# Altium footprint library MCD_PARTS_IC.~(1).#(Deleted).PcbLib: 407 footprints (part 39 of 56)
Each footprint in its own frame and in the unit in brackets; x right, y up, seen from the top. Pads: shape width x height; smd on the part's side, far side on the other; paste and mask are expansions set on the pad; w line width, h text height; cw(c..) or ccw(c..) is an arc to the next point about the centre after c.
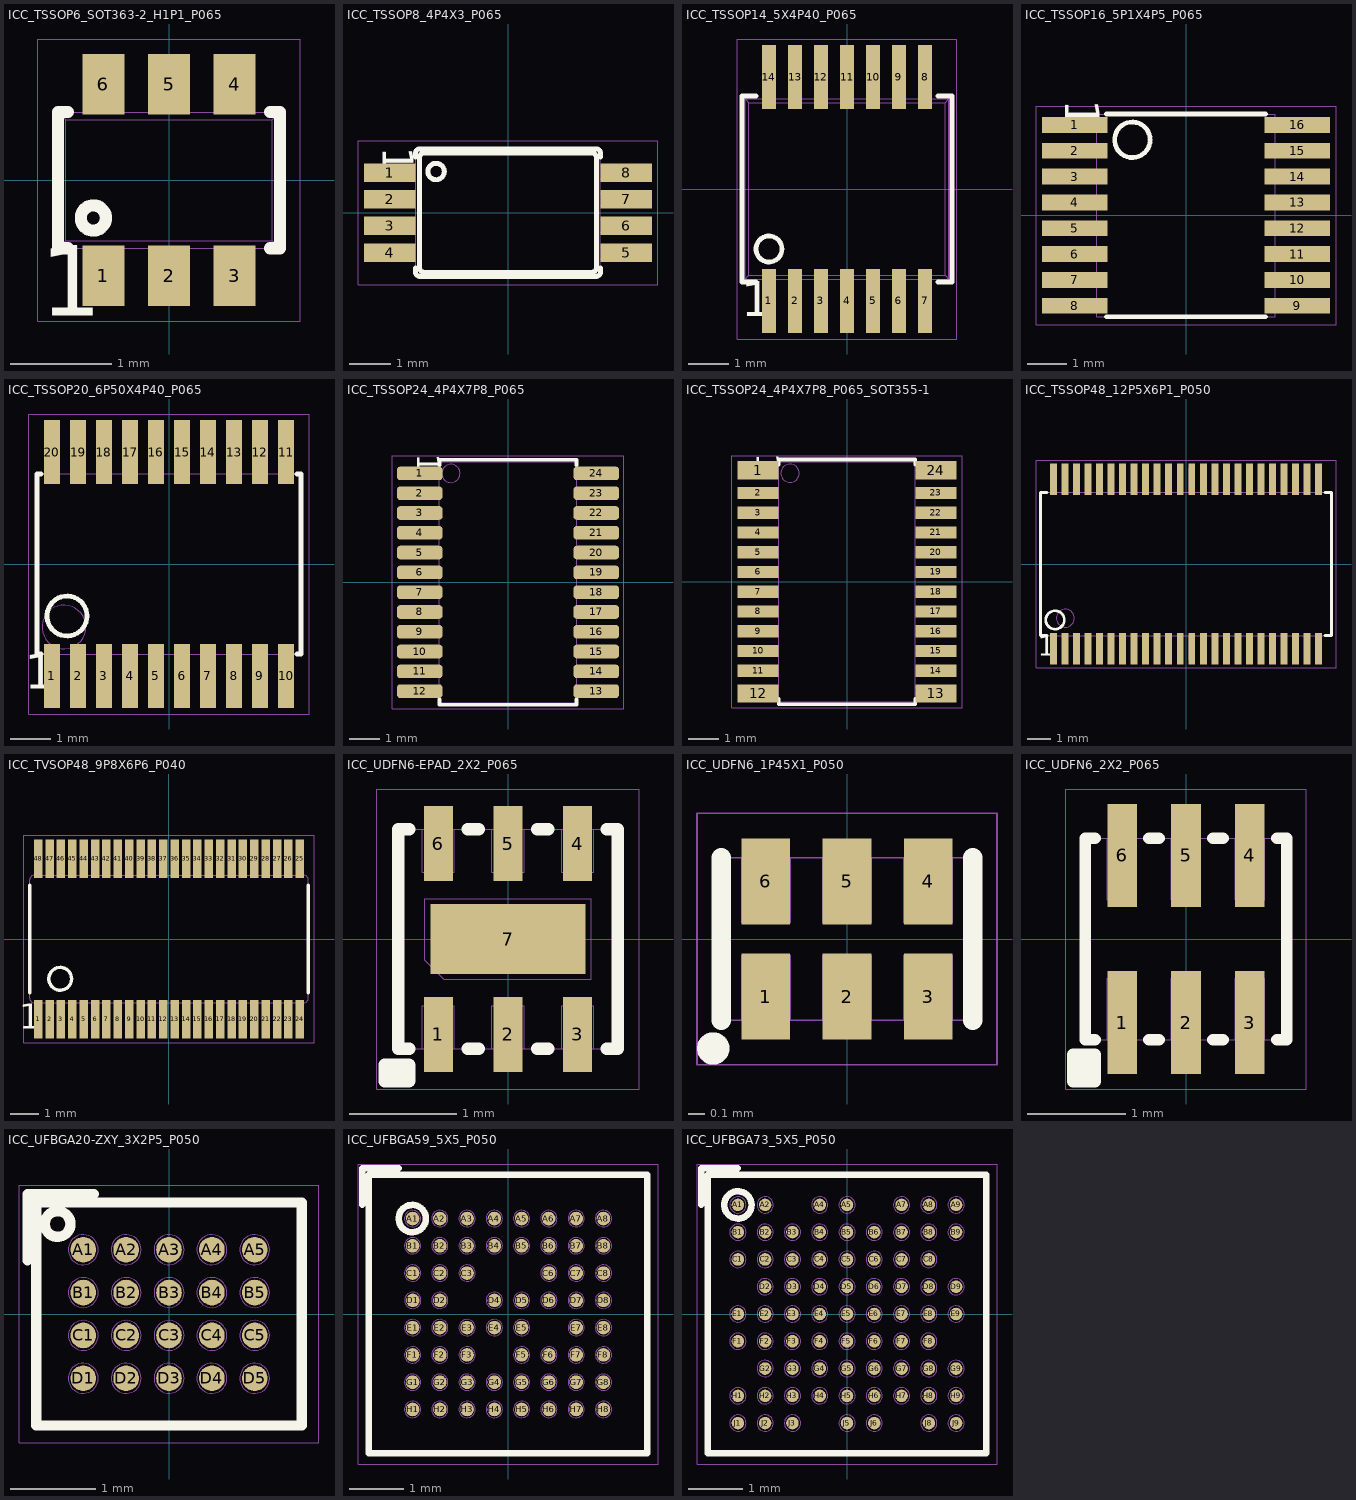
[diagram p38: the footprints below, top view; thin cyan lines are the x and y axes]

## ICC_TSSOP6_SOT363-2_H1P1_P065 [mm]
height 1.1
pads (6):
  rect 0.42x0.6 smd mask+0.05: 1(-0.65,-0.95) 2(0,-0.95) 3(0.65,-0.95) 4(0.65,0.95) 5(0,0.95) 6(-0.65,0.95)
Top Overlay:
  circle w0.12: c-0.75,-0.375 r0.125
  lines w0.12: -1,-0.675 -1.1,-0.675 -1.1,0.675 -1,0.675 ; 1,-0.675 1.1,-0.675 1.1,0.675 1,0.675
  text "1" at -1.275,-1.575 h1.2
M14-Top Assembly:
  circle w0.01: c-0.75,-0.375 r0.125
  lines w0.01: -0.8,-0.675 -0.8,-1.2 -0.5,-1.2 -0.5,-0.675 ; -0.8,0.675 -0.8,1.2 -0.5,1.2 -0.5,0.675 ; -0.15,-0.675 -0.15,-1.2 0.15,-1.2 0.15,-0.675 ; -0.15,0.675 -0.15,1.2 0.15,1.2 0.15,0.675 ; 0.5,-0.675 0.5,-1.2 0.8,-1.2 0.8,-0.675 ; 0.5,0.675 0.5,1.2 0.8,1.2 0.8,0.675 ; -1.1,-0.675 -1.025,-0.6 ; -1.1,-0.675 -1.1,0.675 ; -1.1,-0.675 1.1,-0.675 ; -1.1,0.675 -1.025,0.6 ; -1.1,0.675 1.1,0.675 ; -1.025,-0.6 1.025,-0.6 ; -1.025,-0.6 -1.025,0.6 ; -1.025,0.6 1.025,0.6 ; 1.025,-0.6 1.1,-0.675 ; 1.025,-0.6 1.025,0.6 ; 1.025,0.6 1.1,0.675 ; 1.1,-0.675 1.1,0.675
  text "'.Designator'" at -2,-0.5 h0.75
  text "4" at 0.55,0.725 h0.5
  text "5" at -0.1,0.725 h0.5
  text "6" at -0.75,0.725 h0.5
  text "1" at -0.725,-1.05 h0.5
  text "3" at 0.55,-1.05 h0.5
  text "2" at -0.1,-1.05 h0.5
M16-Top Courtyard:
  lines w0.01: -1.3,-1.4 -1.3,0.35 -1.3,1.4 -0.9,1.4 1.3,1.4 1.3,-1.4 -0.575,-1.4 -1.3,-1.4
3D body "SOT363.STEP": height 1.1, standoff 0, extent -1.1,-1.2 1.1,1.2
3D body: height 1.1, standoff 0, extent -1.1,-0.675 1.1,0.675

## ICC_TSSOP8_4P4X3_P065 [mm] "MCD-01888"
height 1.2
pads (8):
  rect 1.25x0.45 smd mask+0.05: 1(-2.875,0.975) 2(-2.875,0.325) 3(-2.875,-0.325) 4(-2.875,-0.975) 5(2.875,-0.975) 6(2.875,-0.325) 7(2.875,0.325) 8(2.875,0.975)
Top Overlay:
  circle w0.12: c-1.75,1 r0.2
  lines w0.12: -2.25,-1.35 -2.25,-1.45 ccw(c-2.15,-1.45) -2.15,-1.55 2.15,-1.55 ccw(c2.15,-1.45) 2.25,-1.45 2.25,-1.35 ; -2.25,1.35 -2.25,1.45 cw(c-2.15,1.45) -2.15,1.55 2.15,1.55 cw(c2.15,1.45) 2.25,1.45 2.25,1.35 ; -2.15,-1.35 ccw(c-2.05,-1.35) -2.05,-1.45 2.05,-1.45 ccw(c2.05,-1.35) 2.15,-1.35 2.15,1.35 ccw(c2.05,1.35) 2.05,1.45 -2.05,1.45 ccw(c-2.05,1.35) -2.15,1.35 -2.15,-1.35
  text "1" at -3.3,1.6 h1.3
M14-Top Assembly:
  circle w0.01: c-1.75,1 r0.2
  lines w0.01: -2.25,-1.125 -3.3,-1.125 -3.3,-0.825 -2.25,-0.825 ; -2.25,-0.475 -3.3,-0.475 -3.3,-0.175 -2.25,-0.175 ; -2.25,0.175 -3.3,0.175 -3.3,0.475 -2.25,0.475 ; -2.25,0.825 -3.3,0.825 -3.3,1.125 -2.25,1.125 ; 2.25,-1.125 3.3,-1.125 3.3,-0.825 2.25,-0.825 ; 2.25,-0.475 3.3,-0.475 3.3,-0.175 2.25,-0.175 ; 2.25,0.175 3.3,0.175 3.3,0.475 2.25,0.475 ; 2.25,0.825 3.3,0.825 3.3,1.125 2.25,1.125 ; -2.25,-1.45 ccw(c-2.15,-1.45) -2.15,-1.55 2.15,-1.55 ccw(c2.15,-1.45) 2.25,-1.45 2.25,1.45 ccw(c2.15,1.45) 2.15,1.55 -2.15,1.55 ccw(c-2.15,1.45) -2.25,1.45 -2.25,-1.45 ; -2.15,-1.35 ccw(c-2.05,-1.35) -2.05,-1.45 2.05,-1.45 ccw(c2.05,-1.35) 2.15,-1.35 2.15,1.35 ccw(c2.05,1.35) 2.05,1.45 -2.05,1.45 ccw(c-2.05,1.35) -2.15,1.35 -2.15,-1.35
  text "'.Designator'" at -2,-0.5 h0.75
  text "1" at -2.625,0.825 h0.5
  text "4" at -2.725,-1.125 h0.5
  text "5" at 2.5,-1.125 h0.5
  text "8" at 2.5,0.825 h0.5
M16-Top Courtyard:
  lines w0.01: -3.65,-1.75 3.65,-1.75 3.65,1.75 -2.25,1.75 -3.65,1.75 -3.65,-1.75
3D body: height 1.21, standoff 1.2, extent -2.098,0.901 -1.6,1.4
3D body: height 1.2, standoff 0, extent -2.25,-1.55 2.25,1.55
3D body "TSS0P8-1.STEP": height 1.09, standoff 0, extent -3.147,-1.5 3.133,1.5
3D body: height 1.1, standoff 1.09, extent -1.873,0.775 -1.475,1.175

## ICC_TSSOP14_5X4P40_P065 [mm]
height 1.2
pads (14):
  rect 0.35x1.6 smd mask+0.05: 1(-1.95,-2.8) 2(-1.3,-2.8) 3(-0.65,-2.8) 4(0,-2.8) 5(0.65,-2.8) 6(1.3,-2.8) 7(1.95,-2.8) 8(1.95,2.8) 9(1.3,2.8) 10(0.65,2.8) 11(0,2.8) 12(-0.65,2.8) 13(-1.3,2.8) 14(-1.95,2.8)
Top Overlay:
  circle w0.12: c-1.95,-1.5 r0.325
  lines w0.12: -2.275,-2.325 -2.625,-2.325 -2.625,2.325 -2.275,2.325 ; 2.275,-2.325 2.625,-2.325 2.625,2.325 2.275,2.325
  text "1" at -2.65,-3.475 h1.5
M14-Top Assembly:
  lines w0.01: -2.55,2.24 -2.55,-2.25 ; -2.55,-2.25 2.55,-2.25 ; -2.55,-2.25 -2.45,-2.15 ; -2.45,-2.15 2.45,-2.15 ; -2.45,-2.15 -2.45,2.15 ; -2.45,2.15 2.45,2.15 ; -2.45,2.15 -2.55,2.25 2.55,2.25 ; 2.45,-2.15 2.45,2.15 ; 2.45,-2.15 2.55,-2.25 ; 2.45,2.15 2.55,2.25 ; 2.55,-2.25 2.55,2.25 ; -2.075,-3.3 -1.825,-3.3 -1.825,-2.25 -2.075,-2.25 -2.075,-3.3 ; -2.075,2.25 -1.825,2.25 -1.825,3.3 -2.075,3.3 -2.075,2.25 ; -1.425,-3.3 -1.175,-3.3 -1.175,-2.25 -1.425,-2.25 -1.425,-3.3 ; -1.425,2.25 -1.175,2.25 -1.175,3.3 -1.425,3.3 -1.425,2.25 ; -0.775,-3.3 -0.525,-3.3 -0.525,-2.25 -0.775,-2.25 -0.775,-3.3 ; -0.775,2.25 -0.525,2.25 -0.525,3.3 -0.775,3.3 -0.775,2.25 ; -0.125,-3.3 0.125,-3.3 0.125,-2.25 -0.125,-2.25 -0.125,-3.3 ; -0.125,2.25 0.125,2.25 0.125,3.3 -0.125,3.3 -0.125,2.25 ; 0.525,-3.3 0.775,-3.3 0.775,-2.25 0.525,-2.25 0.525,-3.3 ; 0.525,2.25 0.775,2.25 0.775,3.3 0.525,3.3 0.525,2.25 ; 1.175,-3.3 1.425,-3.3 1.425,-2.25 1.175,-2.25 1.175,-3.3 ; 1.175,2.25 1.425,2.25 1.425,3.3 1.175,3.3 1.175,2.25 ; 1.825,-3.3 2.075,-3.3 2.075,-2.25 1.825,-2.25 1.825,-3.3 ; 1.825,2.25 2.075,2.25 2.075,3.3 1.825,3.3 1.825,2.25
  text "'.Designator'" at -2,-0.5 h0.75
  text "8" at 1.75,2.475 h1
  text "14" at -2.35,2.5 h1
  text "1" at -2.075,-3.125 h1
  text "7" at 1.75,-3.1 h1
M16-Top Courtyard:
  lines w0.01: -2.75,-3.75 -2.75,3.75 2.75,3.75 2.75,-3.75 -2.75,-3.75
3D body "TSSOP-14_5X4P40_P065.STEP": height 1.2, standoff 0, extent -2.5,-3.2 2.5,3.2
3D body: height 1.2, standoff 0, extent -2.55,-2.25 2.55,2.25
3D body: height 1.21, standoff 1.2, extent -2.248,-1.799 -1.65,-1.2

## ICC_TSSOP16_5P1X4P5_P065 [mm]
height 1.2
pads (16):
  rect 1.65x0.4 smd mask+0.05: 1(-2.8,2.275) 2(-2.8,1.625) 3(-2.8,0.975) 4(-2.8,0.325) 5(-2.8,-0.325) 6(-2.8,-0.975) 7(-2.8,-1.625) 8(-2.8,-2.275) 9(2.8,-2.275) 10(2.8,-1.625) 11(2.8,-0.975) 12(2.8,-0.325) 13(2.8,0.325) 14(2.8,0.975) 15(2.8,1.625) 16(2.8,2.275)
Top Overlay:
  circle w0.12: c-1.35,1.9 r0.447
  lines w0.12: -2,-2.55 2,-2.55 ; -2,2.55 2,2.55
  text "1" at -3.325,2.925 h1.5
M14-Top Assembly:
  circle w0.01: c-1.35,1.9 r0.447
  lines w0.01: -2.25,-2.425 -3.3,-2.425 -3.3,-2.125 -2.25,-2.125 ; -2.25,-1.775 -3.3,-1.775 -3.3,-1.475 -2.25,-1.475 ; -2.25,-1.125 -3.3,-1.125 -3.3,-0.825 -2.25,-0.825 ; -2.25,-0.475 -3.3,-0.475 -3.3,-0.175 -2.25,-0.175 ; -2.25,0.175 -3.3,0.175 -3.3,0.475 -2.25,0.475 ; -2.25,0.825 -3.3,0.825 -3.3,1.125 -2.25,1.125 ; -2.25,1.475 -3.3,1.475 -3.3,1.775 -2.25,1.775 ; -2.25,2.125 -3.3,2.125 -3.3,2.425 -2.25,2.425 ; 2.25,-2.425 3.3,-2.425 3.3,-2.125 2.25,-2.125 ; 2.25,-1.775 3.3,-1.775 3.3,-1.475 2.25,-1.475 ; 2.25,-1.125 3.3,-1.125 3.3,-0.825 2.25,-0.825 ; 2.25,-0.475 3.3,-0.475 3.3,-0.175 2.25,-0.175 ; 2.25,0.175 3.3,0.175 3.3,0.475 2.25,0.475 ; 2.25,0.825 3.3,0.825 3.3,1.125 2.25,1.125 ; 2.25,1.475 3.3,1.475 3.3,1.775 2.25,1.775 ; 2.25,2.125 3.3,2.125 3.3,2.425 2.25,2.425 ; -2.25,-2.55 2.25,-2.55 2.25,2.55 -2.25,2.55 -2.25,-2.55
  text "'.Designator'" at -2,-0.5 h0.75
  text "1" at -2.875,2.35 h0.75
  text "8" at -2.875,-2.125 h0.75
  text "9" at 2.85,-2.45 h0.75
  text "16" at 2.9,1.95 h0.75
M16-Top Courtyard:
  lines w0.01: -3.775,-2.75 3.775,-2.75 3.775,2.75 -3.775,2.75 -3.775,-2.75
3D body "TSSOP16_5-1X4-5_P065.STEP": height 1, standoff 0, extent -3.2,-2.5 3.2,2.5
3D body: height 1.2, standoff 0, extent -2.255,-2.555 2.255,2.555

## ICC_TSSOP20_6P50X4P40_P065 [mm]
height 1.2
pads (20):
  rect 0.4x1.6 smd mask+0.05: 1(-2.925,-2.8) 2(-2.275,-2.8) 3(-1.625,-2.8) 4(-0.975,-2.8) 5(-0.325,-2.8) 6(0.325,-2.8) 7(0.975,-2.8) 8(1.625,-2.8) 9(2.275,-2.8) 10(2.925,-2.8) 11(2.925,2.8) 12(2.275,2.8) 13(1.625,2.8) 14(0.975,2.8) 15(0.325,2.8) 16(-0.325,2.8) 17(-0.975,2.8) 18(-1.625,2.8) 19(-2.275,2.8) 20(-2.925,2.8)
Top Overlay:
  circle w0.12: c-2.55,-1.3 r0.5
  lines w0.12: -3.2,-2.25 -3.3,-2.25 -3.3,2.25 -3.2,2.25 ; 3.2,-2.25 3.3,-2.25 3.3,2.25 3.2,2.25
  text "1" at -3.6,-3.4 h1.5
M14-Top Assembly:
  circle w0.01: c-2.625,-1.575 r0.548
  lines w0.01: -3.025,-2.25 -3.025,-3.3 -2.825,-3.3 -2.825,-2.25 ; -3.025,2.25 -3.025,3.3 -2.825,3.3 -2.825,2.25 ; -2.375,-2.25 -2.375,-3.3 -2.175,-3.3 -2.175,-2.25 ; -2.375,2.25 -2.375,3.3 -2.175,3.3 -2.175,2.25 ; -1.725,-2.25 -1.725,-3.3 -1.525,-3.3 -1.525,-2.25 ; -1.725,2.25 -1.725,3.3 -1.525,3.3 -1.525,2.25 ; -1.075,-2.25 -1.075,-3.3 -0.875,-3.3 -0.875,-2.25 ; -1.075,2.25 -1.075,3.3 -0.875,3.3 -0.875,2.25 ; -0.425,-2.25 -0.425,-3.3 -0.225,-3.3 -0.225,-2.25 ; -0.425,2.25 -0.425,3.3 -0.225,3.3 -0.225,2.25 ; 0.225,-2.25 0.225,-3.3 0.425,-3.3 0.425,-2.25 ; 0.225,2.25 0.225,3.3 0.425,3.3 0.425,2.25 ; 0.875,-2.25 0.875,-3.3 1.075,-3.3 1.075,-2.25 ; 0.875,2.25 0.875,3.3 1.075,3.3 1.075,2.25 ; 1.525,-2.25 1.525,-3.3 1.725,-3.3 1.725,-2.25 ; 1.525,2.25 1.525,3.3 1.725,3.3 1.725,2.25 ; 2.175,-2.25 2.175,-3.3 2.375,-3.3 2.375,-2.25 ; 2.175,2.25 2.175,3.3 2.375,3.3 2.375,2.25 ; 2.825,-2.25 2.825,-3.3 3.025,-3.3 3.025,-2.25 ; 2.825,2.25 2.825,3.3 3.025,3.3 3.025,2.25 ; -3.3,-2.25 3.3,-2.25 3.3,2.25 -3.3,2.25 -3.3,-2.25
  text "1" at -3.05,-3.075 h1
  text "10" at 2.525,-3.075 h1
  text "11" at 2.55,2.475 h1
  text "20" at -3.375,2.475 h1
  text "'.Designator'" at -2,-0.5 h0.75
M16-Top Courtyard:
  lines w0.01: -3.5,-3.75 3.5,-3.75 3.5,3.75 -3.5,3.75 -3.5,-3.75
3D body "TSSOP20_6P50X4P40_P065.STEP": height 1.2, standoff 0, extent -3.3,-3.3 3.3,3.3
3D body: height 1.2, standoff 0, extent -3.3,-2.25 3.3,2.25
3D body: height 1.21, standoff 1.2, extent -2.973,-1.924 -2.375,-1.326

## ICC_TSSOP24_4P4X7P8_P065 [mm]
height 1.2
pads (24):
  rrect50% 1.5x0.45 smd mask+0.05: 1(-2.9,3.575) 2(-2.9,2.925) 3(-2.9,2.275) 4(-2.9,1.625) 5(-2.9,0.975) 6(-2.9,0.325) 7(-2.9,-0.325) 8(-2.9,-0.975) 9(-2.9,-1.625) 10(-2.9,-2.275) 11(-2.9,-2.925) 12(-2.9,-3.575) 13(2.9,-3.575) 14(2.9,-2.925) 15(2.9,-2.275) 16(2.9,-1.625) 17(2.9,-0.975) 18(2.9,-0.325) 19(2.9,0.325) 20(2.9,0.975) 21(2.9,1.625) 22(2.9,2.275) 23(2.9,2.925) 24(2.9,3.575)
Top Overlay:
  lines w0.12: -2.25,-3.85 -2.25,-4.025 2.25,-4.025 2.25,-3.85 ; -2.25,3.85 -2.25,4.025 2.25,4.025 2.25,3.85
  text "1" at -3.241,4.225 h1.3
M14-Top Assembly:
  circle w0.01: c-1.875,3.575 r0.3
  lines w0.01: -3.3,-3.675 -3.3,-3.475 -2.25,-3.475 -2.25,-3.675 -3.3,-3.675 ; -3.3,-3.025 -3.3,-2.825 -2.25,-2.825 -2.25,-3.025 -3.3,-3.025 ; -3.3,-2.375 -3.3,-2.175 -2.25,-2.175 -2.25,-2.375 -3.3,-2.375 ; -3.3,-1.725 -3.3,-1.525 -2.25,-1.525 -2.25,-1.725 -3.3,-1.725 ; -3.3,-1.075 -3.3,-0.875 -2.25,-0.875 -2.25,-1.075 -3.3,-1.075 ; -3.3,-0.425 -3.3,-0.225 -2.25,-0.225 -2.25,-0.425 -3.3,-0.425 ; -3.3,0.225 -3.3,0.425 -2.25,0.425 -2.25,0.225 -3.3,0.225 ; -3.3,0.875 -3.3,1.075 -2.25,1.075 -2.25,0.875 -3.3,0.875 ; -3.3,1.525 -3.3,1.725 -2.25,1.725 -2.25,1.525 -3.3,1.525 ; -3.3,2.175 -3.3,2.375 -2.25,2.375 -2.25,2.175 -3.3,2.175 ; -3.3,2.825 -3.3,3.025 -2.25,3.025 -2.25,2.825 -3.3,2.825 ; -3.3,3.475 -3.3,3.675 -2.25,3.675 -2.25,3.475 -3.3,3.475 ; -2.25,-3.95 -2.25,3.95 2.25,3.95 2.25,-3.95 -2.25,-3.95 ; 2.25,-3.675 2.25,-3.475 3.3,-3.475 3.3,-3.675 2.25,-3.675 ; 2.25,-3.025 2.25,-2.825 3.3,-2.825 3.3,-3.025 2.25,-3.025 ; 2.25,-2.375 2.25,-2.175 3.3,-2.175 3.3,-2.375 2.25,-2.375 ; 2.25,-1.725 2.25,-1.525 3.3,-1.525 3.3,-1.725 2.25,-1.725 ; 2.25,-1.075 2.25,-0.875 3.3,-0.875 3.3,-1.075 2.25,-1.075 ; 2.25,-0.425 2.25,-0.225 3.3,-0.225 3.3,-0.425 2.25,-0.425 ; 2.25,0.225 2.25,0.425 3.3,0.425 3.3,0.225 2.25,0.225 ; 2.25,0.875 2.25,1.075 3.3,1.075 3.3,0.875 2.25,0.875 ; 2.25,1.525 2.25,1.725 3.3,1.725 3.3,1.525 2.25,1.525 ; 2.25,2.175 2.25,2.375 3.3,2.375 3.3,2.175 2.25,2.175 ; 2.25,2.825 2.25,3.025 3.3,3.025 3.3,2.825 2.25,2.825 ; 2.25,3.475 2.25,3.675 3.3,3.675 3.3,3.475 2.25,3.475
  text "24" at 2.375,4.025 h1
  text "13" at 2.375,-3.15 h1
  text "12" at -3,-3.15 h1
  text "1" at -3.025,3.725 h1
  text "'.Designator'" at -2,-0.5 h0.75
M16-Top Courtyard:
  lines w0.01: -3.8,-4.15 3.8,-4.15 3.8,4.15 -3.8,4.15 -3.8,-4.15
3D body "TSSOP24.STEP": height 1.2, standoff 0, extent -3.278,-3.95 3.278,3.95

## ICC_TSSOP24_4P4X7P8_P065_SOT355-1 [mm] "MCD-04154"
height 1.2
pads (24):
  rect 1.35x0.6 smd mask+0.05: 1(-2.925,3.675) 12(-2.925,-3.675) 13(2.925,-3.675) 24(2.925,3.675)
  rect 1.35x0.4 smd mask+0.05: 2(-2.925,2.925) 3(-2.925,2.275) 4(-2.925,1.625) 5(-2.925,0.975) 6(-2.925,0.325) 7(-2.925,-0.325) 8(-2.925,-0.975) 9(-2.925,-1.625) 10(-2.925,-2.275) 11(-2.925,-2.925) 14(2.925,-2.925) 15(2.925,-2.275) 16(2.925,-1.625) 17(2.925,-0.975) 18(2.925,-0.325) 19(2.925,0.325) 20(2.925,0.975) 21(2.925,1.625) 22(2.925,2.275) 23(2.925,2.925)
Top Overlay:
  lines w0.12: -2.25,-3.85 -2.25,-4.025 2.25,-4.025 2.25,-3.85 ; -2.25,3.85 -2.25,4.025 2.25,4.025 2.25,3.85
  text "1" at -3.241,4.225 h1.3
M14-Top Assembly:
  circle w0.01: c-1.875,3.575 r0.3
  lines w0.01: -3.3,-3.675 -3.3,-3.475 -2.25,-3.475 -2.25,-3.675 -3.3,-3.675 ; -3.3,-3.025 -3.3,-2.825 -2.25,-2.825 -2.25,-3.025 -3.3,-3.025 ; -3.3,-2.375 -3.3,-2.175 -2.25,-2.175 -2.25,-2.375 -3.3,-2.375 ; -3.3,-1.725 -3.3,-1.525 -2.25,-1.525 -2.25,-1.725 -3.3,-1.725 ; -3.3,-1.075 -3.3,-0.875 -2.25,-0.875 -2.25,-1.075 -3.3,-1.075 ; -3.3,-0.425 -3.3,-0.225 -2.25,-0.225 -2.25,-0.425 -3.3,-0.425 ; -3.3,0.225 -3.3,0.425 -2.25,0.425 -2.25,0.225 -3.3,0.225 ; -3.3,0.875 -3.3,1.075 -2.25,1.075 -2.25,0.875 -3.3,0.875 ; -3.3,1.525 -3.3,1.725 -2.25,1.725 -2.25,1.525 -3.3,1.525 ; -3.3,2.175 -3.3,2.375 -2.25,2.375 -2.25,2.175 -3.3,2.175 ; -3.3,2.825 -3.3,3.025 -2.25,3.025 -2.25,2.825 -3.3,2.825 ; -3.3,3.475 -3.3,3.675 -2.25,3.675 -2.25,3.475 -3.3,3.475 ; -2.25,-3.95 -2.25,3.95 2.25,3.95 2.25,-3.95 -2.25,-3.95 ; 2.25,-3.675 2.25,-3.475 3.3,-3.475 3.3,-3.675 2.25,-3.675 ; 2.25,-3.025 2.25,-2.825 3.3,-2.825 3.3,-3.025 2.25,-3.025 ; 2.25,-2.375 2.25,-2.175 3.3,-2.175 3.3,-2.375 2.25,-2.375 ; 2.25,-1.725 2.25,-1.525 3.3,-1.525 3.3,-1.725 2.25,-1.725 ; 2.25,-1.075 2.25,-0.875 3.3,-0.875 3.3,-1.075 2.25,-1.075 ; 2.25,-0.425 2.25,-0.225 3.3,-0.225 3.3,-0.425 2.25,-0.425 ; 2.25,0.225 2.25,0.425 3.3,0.425 3.3,0.225 2.25,0.225 ; 2.25,0.875 2.25,1.075 3.3,1.075 3.3,0.875 2.25,0.875 ; 2.25,1.525 2.25,1.725 3.3,1.725 3.3,1.525 2.25,1.525 ; 2.25,2.175 2.25,2.375 3.3,2.375 3.3,2.175 2.25,2.175 ; 2.25,2.825 2.25,3.025 3.3,3.025 3.3,2.825 2.25,2.825 ; 2.25,3.475 2.25,3.675 3.3,3.675 3.3,3.475 2.25,3.475
  text "24" at 2.375,4.025 h1
  text "13" at 2.375,-3.15 h1
  text "12" at -3,-3.15 h1
  text "1" at -3.025,3.725 h1
  text "'.Designator'" at 0,0 h0.75
M16-Top Courtyard:
  lines w0.01: -3.8,-4.15 3.8,-4.15 3.8,4.15 -3.8,4.15 -3.8,-4.15
3D body "TSSOP24.STEP": height 1.2, standoff 0, extent -3.278,-3.95 3.278,3.95

## ICC_TSSOP48_12P5X6P1_P050 [mm]
height 1.2
pads (48):
  rect 0.3x1.35 smd mask+0.05: 1(-5.75,-3.675) 2(-5.25,-3.675) 3(-4.75,-3.675) 4(-4.25,-3.675) 5(-3.75,-3.675) 6(-3.25,-3.675) 7(-2.75,-3.675) 8(-2.25,-3.675) 9(-1.75,-3.675) 10(-1.25,-3.675) 11(-0.75,-3.675) 12(-0.25,-3.675) 13(0.25,-3.675) 14(0.75,-3.675) 15(1.25,-3.675) 16(1.75,-3.675) 17(2.25,-3.675) 18(2.75,-3.675) 19(3.25,-3.675) 20(3.75,-3.675) 21(4.25,-3.675) 22(4.75,-3.675) 23(5.25,-3.675) 24(5.75,-3.675) 25(5.75,3.675) 26(5.25,3.675) 27(4.75,3.675) 28(4.25,3.675) 29(3.75,3.675) 30(3.25,3.675) 31(2.75,3.675) 32(2.25,3.675) 33(1.75,3.675) 34(1.25,3.675) 35(0.75,3.675) 36(0.25,3.675) 37(-0.25,3.675) 38(-0.75,3.675) 39(-1.25,3.675) 40(-1.75,3.675) 41(-2.25,3.675) 42(-2.75,3.675) 43(-3.25,3.675) 44(-3.75,3.675) 45(-4.25,3.675) 46(-4.75,3.675) 47(-5.25,3.675) 48(-5.75,3.675)
Top Overlay:
  circle w0.12: c-5.675,-2.425 r0.4
  lines w0.12: -6.025,-3.1 -6.3,-3.1 -6.3,3.1 -6.025,3.1 ; 6.025,-3.1 6.3,-3.1 6.3,3.1 6.025,3.1
  text "1" at -6.425,-4.275 h1.5
M14-Top Assembly:
  circle w0.01: c-5.225,-2.35 r0.391
  lines w0.01: -5.85,-3.1 -5.85,-4.15 -5.65,-4.15 -5.65,-3.1 ; -5.85,3.1 -5.85,4.15 -5.65,4.15 -5.65,3.1 ; -5.35,-3.1 -5.35,-4.15 -5.15,-4.15 -5.15,-3.1 ; -5.35,3.1 -5.35,4.15 -5.15,4.15 -5.15,3.1 ; -4.85,-3.1 -4.85,-4.15 -4.65,-4.15 -4.65,-3.1 ; -4.85,3.1 -4.85,4.15 -4.65,4.15 -4.65,3.1 ; -4.35,-3.1 -4.35,-4.15 -4.15,-4.15 -4.15,-3.1 ; -4.35,3.1 -4.35,4.15 -4.15,4.15 -4.15,3.1 ; -3.85,-3.1 -3.85,-4.15 -3.65,-4.15 -3.65,-3.1 ; -3.85,3.1 -3.85,4.15 -3.65,4.15 -3.65,3.1 ; -3.35,-3.1 -3.35,-4.15 -3.15,-4.15 -3.15,-3.1 ; -3.35,3.1 -3.35,4.15 -3.15,4.15 -3.15,3.1 ; -2.85,-3.1 -2.85,-4.15 -2.65,-4.15 -2.65,-3.1 ; -2.85,3.1 -2.85,4.15 -2.65,4.15 -2.65,3.1 ; -2.35,-3.1 -2.35,-4.15 -2.15,-4.15 -2.15,-3.1 ; -2.35,3.1 -2.35,4.15 -2.15,4.15 -2.15,3.1 ; -1.85,-3.1 -1.85,-4.15 -1.65,-4.15 -1.65,-3.1 ; -1.85,3.1 -1.85,4.15 -1.65,4.15 -1.65,3.1 ; -1.35,-3.1 -1.35,-4.15 -1.15,-4.15 -1.15,-3.1 ; -1.35,3.1 -1.35,4.15 -1.15,4.15 -1.15,3.1 ; -0.85,-3.1 -0.85,-4.15 -0.65,-4.15 -0.65,-3.1 ; -0.85,3.1 -0.85,4.15 -0.65,4.15 -0.65,3.1 ; -0.35,-3.1 -0.35,-4.15 -0.15,-4.15 -0.15,-3.1 ; -0.35,3.1 -0.35,4.15 -0.15,4.15 -0.15,3.1 ; 0.15,-3.1 0.15,-4.15 0.35,-4.15 0.35,-3.1 ; 0.15,3.1 0.15,4.15 0.35,4.15 0.35,3.1 ; 0.65,-3.1 0.65,-4.15 0.85,-4.15 0.85,-3.1 ; 0.65,3.1 0.65,4.15 0.85,4.15 0.85,3.1 ; 1.15,-3.1 1.15,-4.15 1.35,-4.15 1.35,-3.1 ; 1.15,3.1 1.15,4.15 1.35,4.15 1.35,3.1 ; 1.65,-3.1 1.65,-4.15 1.85,-4.15 1.85,-3.1 ; 1.65,3.1 1.65,4.15 1.85,4.15 1.85,3.1 ; 2.15,-3.1 2.15,-4.15 2.35,-4.15 2.35,-3.1 ; 2.15,3.1 2.15,4.15 2.35,4.15 2.35,3.1 ; 2.65,-3.1 2.65,-4.15 2.85,-4.15 2.85,-3.1 ; 2.65,3.1 2.65,4.15 2.85,4.15 2.85,3.1 ; 3.15,-3.1 3.15,-4.15 3.35,-4.15 3.35,-3.1 ; 3.15,3.1 3.15,4.15 3.35,4.15 3.35,3.1 ; 3.65,-3.1 3.65,-4.15 3.85,-4.15 3.85,-3.1 ; 3.65,3.1 3.65,4.15 3.85,4.15 3.85,3.1 ; 4.15,-3.1 4.15,-4.15 4.35,-4.15 4.35,-3.1 ; 4.15,3.1 4.15,4.15 4.35,4.15 4.35,3.1 ; 4.65,-3.1 4.65,-4.15 4.85,-4.15 4.85,-3.1 ; 4.65,3.1 4.65,4.15 4.85,4.15 4.85,3.1 ; 5.15,-3.1 5.15,-4.15 5.35,-4.15 5.35,-3.1 ; 5.15,3.1 5.15,4.15 5.35,4.15 5.35,3.1 ; 5.65,-3.1 5.65,-4.15 5.85,-4.15 5.85,-3.1 ; 5.65,3.1 5.65,4.15 5.85,4.15 5.85,3.1 ; -6.3,-3.1 -6.3,3.1 6.3,3.1 6.3,-3.1 -6.3,-3.1
  text "'.Designator'" at -2,-0.5 h0.75
  text "48" at -6.2,3.275 h1
  text "25" at 5.275,3.275 h1
  text "24" at 5.3,-3.925 h1
  text "1" at -5.875,-3.95 h1
M16-Top Courtyard:
  lines w0.01: -6.5,-4.5 6.5,-4.5 6.5,4.5 -6.5,4.5 -6.5,-4.5
3D body: height 1.2, standoff 0, extent -6.299,-3.099 6.299,3.099
3D body "TSSOP48.STEP": height 1.2, standoff 0, extent -6.25,-4.05 6.25,4.05

## ICC_TVSOP48_9P8X6P6_P040 [mm] "MCD-02226"
height 1.2
pads (48):
  rect 0.3x1.35 smd mask+0.05: 1(-4.6,-2.825) 2(-4.2,-2.825) 3(-3.8,-2.825) 4(-3.4,-2.825) 5(-3,-2.825) 6(-2.6,-2.825) 7(-2.2,-2.825) 8(-1.8,-2.825) 9(-1.4,-2.825) 10(-1,-2.825) 11(-0.6,-2.825) 12(-0.2,-2.825) 13(0.2,-2.825) 14(0.6,-2.825) 15(1,-2.825) 16(1.4,-2.825) 17(1.8,-2.825) 18(2.2,-2.825) 19(2.6,-2.825) 20(3,-2.825) 21(3.4,-2.825) 22(3.8,-2.825) 23(4.2,-2.825) 24(4.6,-2.825) 25(4.6,2.825) 26(4.2,2.825) 27(3.8,2.825) 28(3.4,2.825) 29(3,2.825) 30(2.6,2.825) 31(2.2,2.825) 32(1.8,2.825) 33(1.4,2.825) 34(1,2.825) 35(0.6,2.825) 36(0.2,2.825) 37(-0.2,2.825) 38(-0.6,2.825) 39(-1,2.825) 40(-1.4,2.825) 41(-1.8,2.825) 42(-2.2,2.825) 43(-2.6,2.825) 44(-3,2.825) 45(-3.4,2.825) 46(-3.8,2.825) 47(-4.2,2.825) 48(-4.6,2.825)
Top Overlay:
  circle w0.12: c-3.825,-1.4 r0.4
  lines w0.12: -4.9,-1.9 -4.9,1.9 ; 4.9,-1.9 4.9,1.9
  text "1" at -5.275,-3.45 h1.5
M14-Top Assembly:
  drawing of 153 lines, arcs and shapes, not listed
  text "1" at -4.75,-3.1 h1
  text "24" at 4.125,-3.075 h1
  text "25" at 4.15,2.5 h1
  text "48" at -5.1,2.5 h1
  text "'.Designator'" at -2,-0.5 h0.75
M16-Top Courtyard:
  lines w0.01: -5.1,-3.65 -5.1,3.65 5.1,3.65 5.1,-3.65 -5.1,-3.65
3D body: height 1.2, standoff 0, extent -4.9,-2.25 4.9,2.25
3D body "User Library-JEDEC-MO-194.STEP": height 1.2, standoff 0, extent -4.85,-3.2 4.85,3.2

## ICC_UDFN6-EPAD_2X2_P065 [mm] "MCD-02159"
height 0.55
pads (7):
  rect 0.27x0.7 smd mask+0.05: 1(-0.65,-0.89) 2(0,-0.89) 3(0.65,-0.89) 4(0.65,0.89) 5(0,0.89) 6(-0.65,0.89)
  rect 1.45x0.65 smd mask+0.05: 7(0,0)
Top Overlay:
  lines w0.12: -1.125,-1.325 -0.975,-1.175 -0.975,-1.2 -0.95,-1.175 ; -0.925,-1.025 -1.025,-1.025 -1.025,-1 -1.025,1.025 -0.925,1.025 ; -0.375,-1.025 -0.275,-1.025 ; -0.375,1.025 -0.275,1.025 ; 0.275,-1.025 0.375,-1.025 ; 0.275,1.025 0.375,1.025 ; 0.925,-1.025 1.025,-1.025 1.025,1 1.025,1.025 0.925,1.025 ; -1.15,-1.325 -1.15,-1.175 -0.925,-1.175 -0.925,-1.325 -1.15,-1.325
M14-Top Assembly:
  lines w0.01: -0.8,-1.025 -0.8,-0.625 -0.5,-0.625 -0.5,-1.025 ; -0.8,1.025 -0.8,0.625 -0.5,0.625 -0.5,1.025 ; -0.15,-1.025 -0.15,-0.625 0.15,-0.625 0.15,-1.025 ; -0.15,1.025 -0.15,0.625 0.15,0.625 0.15,1.025 ; 0.5,-1.025 0.5,-0.625 0.8,-0.625 0.8,-1.025 ; 0.5,1.025 0.5,0.625 0.8,0.625 0.8,1.025 ; -1.025,-1.025 1.025,-1.025 1.025,1.025 -1.025,1.025 -1.025,-1.025 ; -0.775,-0.2 -0.775,0.375 0.775,0.375 0.775,-0.375 -0.6,-0.375 -0.775,-0.2
  text "7" at -0.125,-0.175 h0.6
  text "'.Designator'" at -2,-0.5 h0.75
  text "1" at -0.725,-1.025 h0.6
  text "2" at -0.125,-1.025 h0.6
  text "3" at 0.525,-1.025 h0.6
  text "4" at 0.525,0.625 h0.6
  text "5" at -0.125,0.625 h0.6
  text "6" at -0.775,0.625 h0.6
M16-Top Courtyard:
  lines w0.01: -1.225,-1.4 -1.225,1.4 1.225,1.4 1.225,-1.4 -1.225,-1.4
3D body: height 0.56, standoff 0.55, extent -0.899,-0.9 -0.6,-0.6
3D body: height 0.55, standoff 0.05, extent -1.025,-1.025 1.025,1.025
3D body: height 0.05, standoff 0, extent -0.8,0.625 -0.5,1.025
3D body: height 0.05, standoff 0, extent -0.775,-0.375 0.775,0.375
3D body: height 0.05, standoff 0, extent -0.15,0.625 0.15,1.025
3D body: height 0.05, standoff 0, extent 0.5,0.625 0.8,1.025
3D body: height 0.05, standoff 0, extent -0.8,-1.025 -0.5,-0.625
3D body: height 0.05, standoff 0, extent -0.15,-1.025 0.15,-0.625
3D body: height 0.05, standoff 0, extent 0.5,-1.025 0.8,-0.625

## ICC_UDFN6_1P45X1_P050 [mm] "MCD-01509"
height 0.55
pads (6):
  rect 0.3x0.53 smd mask+0.05: 1(-0.5,-0.355) 2(0,-0.355) 3(0.5,-0.355) 4(0.5,0.355) 5(0,0.355) 6(-0.5,0.355)
Top Overlay:
  circle w0.1: c-0.825,-0.675 r0.05
  lines w0.12: -0.775,-0.5 -0.775,0.5 ; 0.775,-0.5 0.775,0.5
M14-Top Assembly:
  lines w0.01: -0.65,-0.5 -0.65,-0.1 -0.35,-0.1 -0.35,-0.5 ; -0.65,0.5 -0.65,0.1 -0.35,0.1 -0.35,0.5 ; -0.15,-0.5 -0.15,-0.1 0.15,-0.1 0.15,-0.5 ; -0.15,0.5 -0.15,0.1 0.15,0.1 0.15,0.5 ; 0.35,-0.5 0.35,-0.1 0.65,-0.1 0.65,-0.5 ; 0.35,0.5 0.35,0.1 0.65,0.1 0.65,0.5 ; -0.725,-0.5 -0.725,0.5 0.725,0.5 0.725,-0.5 -0.725,-0.5
  text "6" at -0.6,0.15 h0.5
  text "5" at -0.1,0.15 h0.5
  text "4" at 0.4,0.15 h0.5
  text "3" at 0.4,-0.475 h0.5
  text "2" at -0.1,-0.475 h0.5
  text "1" at -0.575,-0.475 h0.5
  text "'.Designator'" at -2,-0.5 h0.75
M16-Top Courtyard:
  lines w0.01: -0.925,-0.775 0.925,-0.775 0.925,0.775 -0.925,0.775 -0.925,-0.775
3D body: height 0.56, standoff 0.55, extent -0.649,-0.425 -0.35,-0.125
3D body: height 0.55, standoff 0, extent -0.725,-0.5 0.725,0.5

## ICC_UDFN6_2X2_P065 [mm] "MCD-01551"
height 0.55
pads (6):
  rect 0.3x1.05 smd mask+0.05: 1(-0.65,-0.85) 2(0,-0.85) 3(0.65,-0.85) 4(0.65,0.85) 5(0,0.85) 6(-0.65,0.85)
Top Overlay:
  lines w0.12: -1.05,-1.175 -1.05,-1.425 -1.025,-1.45 ; -0.975,-1.45 -0.975,-1.2 -0.95,-1.175 ; -0.925,-1.025 -1.025,-1.025 -1.025,-1 -1.025,1.025 -0.925,1.025 ; -0.375,-1.025 -0.275,-1.025 ; -0.375,1.025 -0.275,1.025 ; 0.275,-1.025 0.375,-1.025 ; 0.275,1.025 0.375,1.025 ; 0.925,-1.025 1.025,-1.025 1.025,1 1.025,1.025 0.925,1.025 ; -1.15,-1.45 -0.925,-1.45 -0.925,-1.175 -1.15,-1.175 -1.15,-1.45
M14-Top Assembly:
  lines w0.01: -0.8,-1.025 -0.8,-0.4 -0.5,-0.4 -0.5,-1.025 ; -0.8,1.025 -0.8,0.4 -0.5,0.4 -0.5,1.025 ; -0.15,-1.025 -0.15,-0.4 0.15,-0.4 0.15,-1.025 ; -0.15,1.025 -0.15,0.4 0.15,0.4 0.15,1.025 ; 0.5,-1.025 0.5,-0.4 0.8,-0.4 0.8,-1.025 ; 0.5,1.025 0.5,0.4 0.8,0.4 0.8,1.025 ; -1.025,-1.025 -1.025,1.025 1.025,1.025 1.025,-1.025 -1.025,-1.025
  text "6" at -0.775,0.525 h0.6
  text "5" at -0.125,0.525 h0.6
  text "4" at 0.525,0.525 h0.6
  text "3" at 0.525,-0.9 h0.6
  text "2" at -0.125,-0.9 h0.6
  text "1" at -0.725,-0.9 h0.6
  text "'.Designator'" at -2,-0.5 h0.75
M16-Top Courtyard:
  lines w0.01: -1.225,-1.525 1.225,-1.525 1.225,1.525 -1.225,1.525 -1.225,-1.525
3D body: height 0.55, standoff 0, extent -1.025,-1.025 1.025,1.025
3D body: height 0.56, standoff 0.55, extent -0.899,-0.9 -0.6,-0.6

## ICC_UFBGA20-ZXY_3X2P5_P050 [mm]
height 0.61
pads (20):
  round 0.3 smd paste+0 mask+0.05: A1(-1,0.75) A2(-0.5,0.75) A3(0,0.75) A4(0.5,0.75) A5(1,0.75) B1(-1,0.25) B2(-0.5,0.25) B3(0,0.25) B4(0.5,0.25) B5(1,0.25) C1(-1,-0.25) C2(-0.5,-0.25) C3(0,-0.25) C4(0.5,-0.25) C5(1,-0.25) D1(-1,-0.75) D2(-0.5,-0.75) D3(0,-0.75) D4(0.5,-0.75) D5(1,-0.75)
Top Overlay:
  circle w0.12: c-1.3,1.05 r0.15
  lines w0.12: -1.65,0.625 -1.65,1.4 -0.875,1.4 ; -1.55,-1.3 -1.55,1.3 1.55,1.3 1.55,-1.3 -1.55,-1.3 ; -1.375,1.3 -1.375,1.3
M14-Top Assembly:
  circle w0.01: c-1,0.75 r0.175
  circle w0.01: c-0.5,0.75 r0.175
  circle w0.01: c0,0.75 r0.175
  circle w0.01: c0.5,0.75 r0.175
  circle w0.01: c1,0.75 r0.175
  circle w0.01: c-1,0.25 r0.175
  circle w0.01: c-0.5,0.25 r0.175
  circle w0.01: c0,0.25 r0.175
  circle w0.01: c0.5,0.25 r0.175
  circle w0.01: c1,0.25 r0.175
  circle w0.01: c-1,-0.25 r0.175
  circle w0.01: c-0.5,-0.25 r0.175
  circle w0.01: c0,-0.25 r0.175
  circle w0.01: c0.5,-0.25 r0.175
  circle w0.01: c1,-0.25 r0.175
  circle w0.01: c-1,-0.75 r0.175
  circle w0.01: c-0.5,-0.75 r0.175
  circle w0.01: c0,-0.75 r0.175
  circle w0.01: c0.5,-0.75 r0.175
  circle w0.01: c1,-0.75 r0.175
  lines w0.01: -1.55,-1.3 1.55,-1.3 1.55,1.3 -1.55,1.3 -1.55,-1.3
  text "A1" at -1.275,0.6 h0.5
  text "'.Designator'" at -2,-0.5 h0.75
M16-Top Courtyard:
  lines w0.01: -1.75,-1.5 1.75,-1.5 1.75,1.5 -1.75,1.5 -1.75,-1.5
3D body "UFBGA20-P050.STEP": height 0.59, standoff -0.03, extent -1.55,-1.3 1.55,1.3
3D body: height 0.61, standoff 0, extent -1.555,-1.305 1.555,1.305

## ICC_UFBGA59_5X5_P050 [mm] "MCD-02745"
height 0.6
pads (59):
  round 0.25 smd mask+0.038: A1(-1.75,1.75) A2(-1.25,1.75) A3(-0.75,1.75) A4(-0.25,1.75) A5(0.25,1.75) A6(0.745,1.75) A7(1.25,1.75) A8(1.75,1.75) B1(-1.75,1.25) B2(-1.25,1.25) B3(-0.75,1.25) B4(-0.25,1.25) B5(0.25,1.25) B6(0.75,1.25) B7(1.25,1.25) B8(1.75,1.25) C1(-1.75,0.75) C2(-1.25,0.75) C3(-0.75,0.75) C6(0.75,0.75) C7(1.25,0.75) C8(1.75,0.75) D1(-1.745,0.25) D2(-1.25,0.25) D4(-0.25,0.25) D5(0.25,0.25) D6(0.75,0.25) D7(1.25,0.25) D8(1.75,0.25) E1(-1.75,-0.25) E2(-1.25,-0.25) E3(-0.75,-0.25) E4(-0.25,-0.25) E5(0.25,-0.25) E7(1.25,-0.25) E8(1.75,-0.25) F1(-1.75,-0.75) F2(-1.25,-0.75) F3(-0.75,-0.75) F5(0.25,-0.75) F6(0.75,-0.75) F7(1.25,-0.75) F8(1.75,-0.75) G1(-1.75,-1.25) G2(-1.25,-1.25) G3(-0.75,-1.25) G4(-0.25,-1.25) G5(0.25,-1.25) G6(0.75,-1.25) G7(1.25,-1.25) G8(1.75,-1.25) H1(-1.75,-1.75) H2(-1.25,-1.75) H3(-0.75,-1.75) H4(-0.25,-1.75) H5(0.25,-1.75) H6(0.75,-1.75) H7(1.25,-1.75) H8(1.75,-1.75)
Top Overlay:
  circle w0.12: c-1.755,1.75 r0.25
  lines w0.12: -2.675,2 -2.675,2.675 -2,2.675 ; -2.55,-2.55 2.55,-2.55 2.55,2.55 -2.55,2.55 -2.55,-2.55
M14-Top Assembly:
  circle w0.01: c-1.745,0.25 r0.15
  circle w0.01: c0.75,1.75 r0.15
  circle w0.01: c-0.75,1.75 r0.15
  circle w0.01: c0.75,-1.75 r0.15
  circle w0.01: c0.75,-1.25 r0.15
  circle w0.01: c0.75,-0.75 r0.15
  circle w0.01: c0.75,0.25 r0.15
  circle w0.01: c0.75,0.75 r0.15
  circle w0.01: c0.75,1.25 r0.15
  circle w0.01: c-1.75,1.75 r0.15
  circle w0.01: c-1.25,1.75 r0.15
  circle w0.01: c-0.25,1.75 r0.15
  circle w0.01: c0.25,1.75 r0.15
  circle w0.01: c1.25,1.75 r0.15
  circle w0.01: c1.75,1.75 r0.15
  circle w0.01: c-1.75,1.25 r0.15
  circle w0.01: c-1.25,1.25 r0.15
  circle w0.01: c-0.75,1.25 r0.15
  circle w0.01: c-0.25,1.25 r0.15
  circle w0.01: c0.25,1.25 r0.15
  circle w0.01: c1.25,1.25 r0.15
  circle w0.01: c1.75,1.25 r0.15
  circle w0.01: c-0.75,0.75 r0.15
  circle w0.01: c1.75,0.25 r0.15
  circle w0.01: c1.25,0.25 r0.15
  circle w0.01: c0.25,0.25 r0.15
  circle w0.01: c-0.25,0.25 r0.15
  circle w0.01: c-1.25,0.25 r0.15
  circle w0.01: c1.75,0.75 r0.15
  circle w0.01: c1.25,0.75 r0.15
  circle w0.01: c-1.25,0.75 r0.15
  circle w0.01: c-1.75,0.75 r0.15
  circle w0.01: c-1.25,-1.25 r0.15
  circle w0.01: c-0.25,-1.25 r0.15
  circle w0.01: c0.25,-1.25 r0.15
  circle w0.01: c1.25,-1.25 r0.15
  circle w0.01: c1.75,-1.25 r0.15
  circle w0.01: c-1.75,-1.75 r0.15
  circle w0.01: c-1.25,-1.75 r0.15
  circle w0.01: c-0.75,-1.75 r0.15
  circle w0.01: c-0.25,-1.75 r0.15
  circle w0.01: c0.25,-1.75 r0.15
  circle w0.01: c1.25,-1.75 r0.15
  circle w0.01: c1.75,-1.75 r0.15
  circle w0.01: c-0.75,-1.25 r0.15
  circle w0.01: c-0.75,-0.25 r0.15
  circle w0.01: c1.75,-0.75 r0.15
  circle w0.01: c1.25,-0.75 r0.15
  circle w0.01: c0.25,-0.75 r0.15
  circle w0.01: c-0.75,-0.75 r0.15
  circle w0.01: c-1.25,-0.75 r0.15
  circle w0.01: c-1.75,-0.75 r0.15
  circle w0.01: c1.75,-0.25 r0.15
  circle w0.01: c1.25,-0.25 r0.15
  circle w0.01: c0.25,-0.25 r0.15
  circle w0.01: c-0.25,-0.25 r0.15
  circle w0.01: c-1.25,-0.25 r0.15
  circle w0.01: c-1.75,-0.25 r0.15
  circle w0.01: c-1.75,-1.25 r0.15
  lines w0.01: -2.55,-2.55 -2.55,2.55 2.55,2.55 2.55,-2.55 -2.55,-2.55
  text "A1" at -1.9,1.65 h0.3
  text "'.Designator'" at 0,0 h0.75
M16-Top Courtyard:
  lines w0.01: -2.75,-2.75 -2.75,2.75 2.75,2.75 2.75,-2.75 -2.75,-2.75
3D body: height 0.25, standoff -0.05, extent -1.886,0.107 -1.605,0.393
3D body: height 0.25, standoff -0.05, extent 0.609,1.607 0.891,1.893
3D body: height 0.25, standoff -0.05, extent -0.891,1.607 -0.609,1.893
3D body: height 0.25, standoff -0.05, extent 0.609,-1.893 0.891,-1.607
3D body: height 0.25, standoff -0.05, extent 0.609,-1.393 0.891,-1.107
3D body: height 0.25, standoff -0.05, extent 0.609,-0.893 0.891,-0.607
3D body: height 0.25, standoff -0.05, extent 0.609,0.107 0.891,0.393
3D body: height 0.25, standoff -0.05, extent 0.609,0.607 0.891,0.893
3D body: height 0.25, standoff -0.05, extent 0.609,1.107 0.891,1.393
3D body: height 0.6, standoff 0.15, extent -2.55,-2.525 2.55,2.55
3D body: height 0.61, standoff 0.6, extent -2.052,1.451 -1.454,2.049
3D body: height 0.25, standoff -0.05, extent -1.891,1.607 -1.609,1.893
3D body: height 0.25, standoff -0.05, extent -1.391,1.607 -1.109,1.893
3D body: height 0.25, standoff -0.05, extent -0.391,1.607 -0.109,1.893
3D body: height 0.25, standoff -0.05, extent 0.109,1.607 0.391,1.893
3D body: height 0.25, standoff -0.05, extent 1.109,1.607 1.391,1.893
3D body: height 0.25, standoff -0.05, extent 1.609,1.607 1.891,1.893
3D body: height 0.25, standoff -0.05, extent -1.891,1.107 -1.609,1.393
3D body: height 0.25, standoff -0.05, extent -1.391,1.107 -1.109,1.393
3D body: height 0.25, standoff -0.05, extent -0.891,1.107 -0.609,1.393
3D body: height 0.25, standoff -0.05, extent -0.391,1.107 -0.109,1.393
3D body: height 0.25, standoff -0.05, extent 0.109,1.107 0.391,1.393
3D body: height 0.25, standoff -0.05, extent 1.109,1.107 1.391,1.393
3D body: height 0.25, standoff -0.05, extent 1.609,1.107 1.891,1.393
3D body: height 0.25, standoff -0.05, extent -0.891,0.607 -0.609,0.893
3D body: height 0.25, standoff -0.05, extent 1.609,0.107 1.891,0.393
3D body: height 0.25, standoff -0.05, extent 1.109,0.107 1.391,0.393
3D body: height 0.25, standoff -0.05, extent 0.109,0.107 0.391,0.393
3D body: height 0.25, standoff -0.05, extent -0.391,0.107 -0.109,0.393
3D body: height 0.25, standoff -0.05, extent -1.391,0.107 -1.109,0.393
3D body: height 0.25, standoff -0.05, extent 1.609,0.607 1.891,0.893
3D body: height 0.25, standoff -0.05, extent 1.109,0.607 1.391,0.893
3D body: height 0.25, standoff -0.05, extent -1.391,0.607 -1.109,0.893
3D body: height 0.25, standoff -0.05, extent -1.891,0.607 -1.609,0.893
3D body: height 0.25, standoff -0.05, extent -1.391,-1.393 -1.109,-1.107
3D body: height 0.25, standoff -0.05, extent -0.391,-1.393 -0.109,-1.107
3D body: height 0.25, standoff -0.05, extent 0.109,-1.393 0.391,-1.107
3D body: height 0.25, standoff -0.05, extent 1.109,-1.393 1.391,-1.107
3D body: height 0.25, standoff -0.05, extent 1.609,-1.393 1.891,-1.107
3D body: height 0.25, standoff -0.05, extent -1.891,-1.893 -1.609,-1.607
3D body: height 0.25, standoff -0.05, extent -1.391,-1.893 -1.109,-1.607
3D body: height 0.25, standoff -0.05, extent -0.891,-1.893 -0.609,-1.607
3D body: height 0.25, standoff -0.05, extent -0.391,-1.893 -0.109,-1.607
3D body: height 0.25, standoff -0.05, extent 0.109,-1.893 0.391,-1.607
3D body: height 0.25, standoff -0.05, extent 1.109,-1.893 1.391,-1.607
3D body: height 0.25, standoff -0.05, extent 1.609,-1.893 1.891,-1.607
3D body: height 0.25, standoff -0.05, extent -0.891,-1.393 -0.609,-1.107
3D body: height 0.25, standoff -0.05, extent -0.891,-0.393 -0.609,-0.107
3D body: height 0.25, standoff -0.05, extent 1.609,-0.893 1.891,-0.607
3D body: height 0.25, standoff -0.05, extent 1.109,-0.893 1.391,-0.607
3D body: height 0.25, standoff -0.05, extent 0.109,-0.893 0.391,-0.607
3D body: height 0.25, standoff -0.05, extent -0.891,-0.893 -0.609,-0.607
3D body: height 0.25, standoff -0.05, extent -1.391,-0.893 -1.109,-0.607
3D body: height 0.25, standoff -0.05, extent -1.891,-0.893 -1.609,-0.607
3D body: height 0.25, standoff -0.05, extent 1.609,-0.393 1.891,-0.107
3D body: height 0.25, standoff -0.05, extent 1.109,-0.393 1.391,-0.107
3D body: height 0.25, standoff -0.05, extent 0.109,-0.393 0.391,-0.107
3D body: height 0.25, standoff -0.05, extent -0.391,-0.393 -0.109,-0.107
3D body: height 0.25, standoff -0.05, extent -1.391,-0.393 -1.109,-0.107
3D body: height 0.25, standoff -0.05, extent -1.891,-0.393 -1.609,-0.107
3D body: height 0.25, standoff -0.05, extent -1.891,-1.393 -1.609,-1.107

## ICC_UFBGA73_5X5_P050 [mm] "MCD-01435"
height 0.6
pads (73):
  round 0.23 smd mask+0.05: A1(-2,2) A2(-1.5,2) A4(-0.5,2) A5(0,2) A7(1,2) A8(1.5,2) A9(2,2) B1(-2,1.5) B2(-1.5,1.5) B3(-1,1.5) B4(-0.5,1.5) B5(0,1.5) B6(0.5,1.5) B7(1,1.5) B8(1.5,1.5) B9(2,1.5) C1(-2,1) C2(-1.5,1) C3(-1,1) C4(-0.5,1) C5(0,1) C6(0.5,1) C7(1,1) C8(1.5,1) D2(-1.5,0.5) D3(-1,0.5) D4(-0.5,0.5) D5(0,0.5) D6(0.5,0.5) D7(1,0.5) D8(1.5,0.5) D9(2,0.5) E1(-2,0) E2(-1.5,0) E3(-1,0) E4(-0.5,0) E5(0,0) E6(0.5,0) E7(1,0) E8(1.5,0) E9(2,0) F1(-2,-0.5) F2(-1.5,-0.5) F3(-1,-0.5) F4(-0.5,-0.5) F5(0,-0.5) F6(0.5,-0.5) F7(1,-0.5) F8(1.5,-0.5) G2(-1.5,-1) G3(-1,-1) G4(-0.5,-1) G5(0,-1) G6(0.5,-1) G7(1,-1) G8(1.5,-1) G9(2,-1) H1(-2,-1.5) H2(-1.5,-1.5) H3(-1,-1.5) H4(-0.5,-1.5) H5(0,-1.5) H6(0.5,-1.5) H7(1,-1.5) H8(1.5,-1.5) H9(2,-1.5) J1(-2,-2) J2(-1.5,-2) J3(-1,-2) J5(0,-2) J6(0.5,-2) J8(1.5,-2) J9(2,-2)
Top Overlay:
  circle w0.12: c-2,2 r0.25
  lines w0.12: -2.675,2 -2.675,2.675 -2,2.675 ; -2.55,-2.55 2.55,-2.55 2.55,2.55 -2.55,2.55 -2.55,-2.55
M14-Top Assembly:
  circle w0.01: c-2,2 r0.15
  circle w0.01: c-1.5,2 r0.15
  circle w0.01: c-0.5,2 r0.15
  circle w0.01: c0,2 r0.15
  circle w0.01: c1,2 r0.15
  circle w0.01: c1.5,2 r0.15
  circle w0.01: c2,2 r0.15
  circle w0.01: c-2,1.5 r0.15
  circle w0.01: c-1.5,1.5 r0.15
  circle w0.01: c-1,1.5 r0.15
  circle w0.01: c-0.5,1.5 r0.15
  circle w0.01: c0,1.5 r0.15
  circle w0.01: c0.5,1.5 r0.15
  circle w0.01: c1,1.5 r0.15
  circle w0.01: c1.5,1.5 r0.15
  circle w0.01: c2,1.5 r0.15
  circle w0.01: c-1,1 r0.15
  circle w0.01: c0.5,1 r0.15
  circle w0.01: c2,0.5 r0.15
  circle w0.01: c1.5,0.5 r0.15
  circle w0.01: c1,0.5 r0.15
  circle w0.01: c0.5,0.5 r0.15
  circle w0.01: c0,0.5 r0.15
  circle w0.01: c-0.5,0.5 r0.15
  circle w0.01: c-1,0.5 r0.15
  circle w0.01: c-1.5,0.5 r0.15
  circle w0.01: c1.5,1 r0.15
  circle w0.01: c1,1 r0.15
  circle w0.01: c0,1 r0.15
  circle w0.01: c-0.5,1 r0.15
  circle w0.01: c-1.5,1 r0.15
  circle w0.01: c-2,1 r0.15
  circle w0.01: c-1.5,-1 r0.15
  circle w0.01: c-0.5,-1 r0.15
  circle w0.01: c0,-1 r0.15
  circle w0.01: c1,-1 r0.15
  circle w0.01: c1.5,-1 r0.15
  circle w0.01: c2,-1 r0.15
  circle w0.01: c-2,-1.5 r0.15
  circle w0.01: c-1.5,-1.5 r0.15
  circle w0.01: c-1,-1.5 r0.15
  circle w0.01: c-0.5,-1.5 r0.15
  circle w0.01: c0,-1.5 r0.15
  circle w0.01: c0.5,-1.5 r0.15
  circle w0.01: c1,-1.5 r0.15
  circle w0.01: c1.5,-1.5 r0.15
  circle w0.01: c2,-1.5 r0.15
  circle w0.01: c0.5,-1 r0.15
  circle w0.01: c-1,-1 r0.15
  circle w0.01: c-1,0 r0.15
  circle w0.01: c0.5,0 r0.15
  circle w0.01: c1.5,-0.5 r0.15
  circle w0.01: c1,-0.5 r0.15
  circle w0.01: c0.5,-0.5 r0.15
  circle w0.01: c0,-0.5 r0.15
  circle w0.01: c-0.5,-0.5 r0.15
  circle w0.01: c-1,-0.5 r0.15
  circle w0.01: c-1.5,-0.5 r0.15
  circle w0.01: c-2,-0.5 r0.15
  circle w0.01: c2,0 r0.15
  circle w0.01: c1.5,0 r0.15
  circle w0.01: c1,0 r0.15
  circle w0.01: c0,0 r0.15
  circle w0.01: c-0.5,0 r0.15
  circle w0.01: c-1.5,0 r0.15
  circle w0.01: c-2,0 r0.15
  circle w0.01: c2,-2 r0.15
  circle w0.01: c1.5,-2 r0.15
  circle w0.01: c0.5,-2 r0.15
  circle w0.01: c0,-2 r0.15
  circle w0.01: c-1,-2 r0.15
  circle w0.01: c-1.5,-2 r0.15
  circle w0.01: c-2,-2 r0.15
  lines w0.01: -2.55,-2.55 -2.55,2.55 2.55,2.55 2.55,-2.55 -2.55,-2.55
  text "H7" at 0.85,-1.6 h0.3
  text "H4" at -0.65,-1.6 h0.3
  text "B6" at 0.35,1.4 h0.3
  text "B3" at -1.15,1.4 h0.3
  text "F8" at 1.375,-0.6 h0.3
  text "G2" at -1.65,-1.1 h0.3
  text "D2" at -1.65,0.4 h0.3
  text "C8" at 1.35,0.9 h0.3
  text "G9" at 1.825,-1.1 h0.3
  text "H9" at 1.85,-1.6 h0.3
  text "D9" at 1.85,0.4 h0.3
  text "E9" at 1.85,-0.1 h0.3
  text "B9" at 1.85,1.4 h0.3
  text "H1" at -2.15,-1.6 h0.3
  text "E1" at -2.125,-0.1 h0.3
  text "F1" at -2.125,-0.6 h0.3
  text "C1" at -2.15,0.9 h0.3
  text "J8" at 1.375,-2.1 h0.3
  text "J5" at -0.125,-2.1 h0.3
  text "J6" at 0.375,-2.1 h0.3
  text "J3" at -1.125,-2.1 h0.3
  text "A7" at 0.85,1.9 h0.3
  text "A8" at 1.35,1.9 h0.3
  text "A4" at -0.65,1.9 h0.3
  text "A5" at -0.15,1.9 h0.3
  text "J9" at 1.875,-2.1 h0.3
  text "J2" at -1.625,-2.1 h0.3
  text "J1" at -2.125,-2.1 h0.3
  text "B1" at -2.125,1.4 h0.3
  text "A9" at 1.85,1.9 h0.3
  text "A2" at -1.65,1.9 h0.3
  text "A1" at -2.15,1.9 h0.3
  text "'.Designator'" at -2,1.85 h0.75
M16-Top Courtyard:
  lines w0.01: -2.75,-2.75 -2.75,2.75 2.75,2.75 2.75,-2.75 -2.75,-2.75
3D body: height 0.6, standoff 0.15, extent -2.55,-2.525 2.55,2.55
3D body: height 0.61, standoff 0.6, extent -2.298,1.701 -1.7,2.3
3D body: height 0.25, standoff -0.05, extent -2.136,1.857 -1.855,2.143
3D body: height 0.25, standoff -0.05, extent -1.636,1.857 -1.355,2.143
3D body: height 0.25, standoff -0.05, extent -0.636,1.857 -0.355,2.143
3D body: height 0.25, standoff -0.05, extent -0.136,1.857 0.145,2.143
3D body: height 0.25, standoff -0.05, extent 0.864,1.857 1.145,2.143
3D body: height 0.25, standoff -0.05, extent 1.364,1.857 1.645,2.143
3D body: height 0.25, standoff -0.05, extent 1.864,1.857 2.145,2.143
3D body: height 0.25, standoff -0.05, extent -2.136,1.357 -1.855,1.643
3D body: height 0.25, standoff -0.05, extent -1.636,1.357 -1.355,1.643
3D body: height 0.25, standoff -0.05, extent -1.136,1.357 -0.855,1.643
3D body: height 0.25, standoff -0.05, extent -0.636,1.357 -0.355,1.643
3D body: height 0.25, standoff -0.05, extent -0.136,1.357 0.145,1.643
3D body: height 0.25, standoff -0.05, extent 0.364,1.357 0.645,1.643
3D body: height 0.25, standoff -0.05, extent 0.864,1.357 1.145,1.643
3D body: height 0.25, standoff -0.05, extent 1.364,1.357 1.645,1.643
3D body: height 0.25, standoff -0.05, extent 1.864,1.357 2.145,1.643
3D body: height 0.25, standoff -0.05, extent -1.136,0.857 -0.855,1.143
3D body: height 0.25, standoff -0.05, extent 0.364,0.857 0.645,1.143
3D body: height 0.25, standoff -0.05, extent 1.864,0.357 2.145,0.643
3D body: height 0.25, standoff -0.05, extent 1.364,0.357 1.645,0.643
3D body: height 0.25, standoff -0.05, extent 0.864,0.357 1.145,0.643
3D body: height 0.25, standoff -0.05, extent 0.364,0.357 0.645,0.643
3D body: height 0.25, standoff -0.05, extent -0.136,0.357 0.145,0.643
3D body: height 0.25, standoff -0.05, extent -0.636,0.357 -0.355,0.643
3D body: height 0.25, standoff -0.05, extent -1.136,0.357 -0.855,0.643
3D body: height 0.25, standoff -0.05, extent -1.636,0.357 -1.355,0.643
3D body: height 0.25, standoff -0.05, extent 1.364,0.857 1.645,1.143
3D body: height 0.25, standoff -0.05, extent 0.864,0.857 1.145,1.143
3D body: height 0.25, standoff -0.05, extent -0.136,0.857 0.145,1.143
3D body: height 0.25, standoff -0.05, extent -0.636,0.857 -0.355,1.143
3D body: height 0.25, standoff -0.05, extent -1.636,0.857 -1.355,1.143
3D body: height 0.25, standoff -0.05, extent -2.136,0.857 -1.855,1.143
3D body: height 0.25, standoff -0.05, extent -1.636,-1.143 -1.355,-0.857
3D body: height 0.25, standoff -0.05, extent -0.636,-1.143 -0.355,-0.857
3D body: height 0.25, standoff -0.05, extent -0.136,-1.143 0.145,-0.857
3D body: height 0.25, standoff -0.05, extent 0.864,-1.143 1.145,-0.857
3D body: height 0.25, standoff -0.05, extent 1.364,-1.143 1.645,-0.857
3D body: height 0.25, standoff -0.05, extent 1.864,-1.143 2.145,-0.857
3D body: height 0.25, standoff -0.05, extent -2.136,-1.643 -1.855,-1.357
3D body: height 0.25, standoff -0.05, extent -1.636,-1.643 -1.355,-1.357
3D body: height 0.25, standoff -0.05, extent -1.136,-1.643 -0.855,-1.357
3D body: height 0.25, standoff -0.05, extent -0.636,-1.643 -0.355,-1.357
3D body: height 0.25, standoff -0.05, extent -0.136,-1.643 0.145,-1.357
3D body: height 0.25, standoff -0.05, extent 0.364,-1.643 0.645,-1.357
3D body: height 0.25, standoff -0.05, extent 0.864,-1.643 1.145,-1.357
3D body: height 0.25, standoff -0.05, extent 1.364,-1.643 1.645,-1.357
3D body: height 0.25, standoff -0.05, extent 1.864,-1.643 2.145,-1.357
3D body: height 0.25, standoff -0.05, extent 0.364,-1.143 0.645,-0.857
3D body: height 0.25, standoff -0.05, extent -1.136,-1.143 -0.855,-0.857
3D body: height 0.25, standoff -0.05, extent -1.136,-0.143 -0.855,0.143
3D body: height 0.25, standoff -0.05, extent 0.364,-0.143 0.645,0.143
3D body: height 0.25, standoff -0.05, extent 1.364,-0.643 1.645,-0.357
3D body: height 0.25, standoff -0.05, extent 0.864,-0.643 1.145,-0.357
3D body: height 0.25, standoff -0.05, extent 0.364,-0.643 0.645,-0.357
3D body: height 0.25, standoff -0.05, extent -0.136,-0.643 0.145,-0.357
3D body: height 0.25, standoff -0.05, extent -0.636,-0.643 -0.355,-0.357
3D body: height 0.25, standoff -0.05, extent -1.136,-0.643 -0.855,-0.357
3D body: height 0.25, standoff -0.05, extent -1.636,-0.643 -1.355,-0.357
3D body: height 0.25, standoff -0.05, extent -2.136,-0.643 -1.855,-0.357
3D body: height 0.25, standoff -0.05, extent 1.864,-0.143 2.145,0.143
3D body: height 0.25, standoff -0.05, extent 1.364,-0.143 1.645,0.143
3D body: height 0.25, standoff -0.05, extent 0.864,-0.143 1.145,0.143
3D body: height 0.25, standoff -0.05, extent -0.136,-0.143 0.145,0.143
3D body: height 0.25, standoff -0.05, extent -0.636,-0.143 -0.355,0.143
3D body: height 0.25, standoff -0.05, extent -1.636,-0.143 -1.355,0.143
3D body: height 0.25, standoff -0.05, extent -2.136,-0.143 -1.855,0.143
3D body: height 0.25, standoff -0.05, extent 1.864,-2.143 2.145,-1.857
3D body: height 0.25, standoff -0.05, extent 1.364,-2.143 1.645,-1.857
3D body: height 0.25, standoff -0.05, extent 0.364,-2.143 0.645,-1.857
3D body: height 0.25, standoff -0.05, extent -0.136,-2.143 0.145,-1.857
3D body: height 0.25, standoff -0.05, extent -1.136,-2.143 -0.855,-1.857
3D body: height 0.25, standoff -0.05, extent -1.636,-2.143 -1.355,-1.857
3D body: height 0.25, standoff -0.05, extent -2.136,-2.143 -1.855,-1.857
